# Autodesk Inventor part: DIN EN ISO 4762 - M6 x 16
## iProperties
Created: 2007-08
Part Number: DIN EN ISO 4762 - M6 x 16
Material: Stahl, weich, unlegiert
Description: Innensechskantschraube
Vendor: Autodesk Inc.
Document SubType Name: Modeling
Standard: ISO 4762
Designer: Ulrich
Standards Organization: DIN
Language: de-DE
Size Designation: M6 x 16
Categories: <MemberInstance Version="R10.0.0"><Categories><Category DisplayName="Schrauben" InternalName="e4da775c-781d-43d5-af7c-5136215cf5a6" Mnemonic="FSTN"><Category Di
Author: Ulrich
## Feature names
1. Körper [Revolution]
2. Loch [Extrusion]
3. Rundung1 [Fillet]
4. Fase1 [Chamfer]
